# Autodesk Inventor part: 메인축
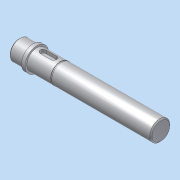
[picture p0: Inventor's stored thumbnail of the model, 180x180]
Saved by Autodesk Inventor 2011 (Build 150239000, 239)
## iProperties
Company: 한국ATC센터
Created: 2014-12
Part Number: 메인축
Document SubType Name: Modeling
Designer: KYOUNG IL JANG
Density: 1 g/cm^3
Mass: 27.2374 g
Surface Area: 71.2962 cm^2
Volume: 27.2374 cm^3
Author: KYOUNG IL JANG
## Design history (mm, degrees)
sketch "스케치1"
  geometry: L1 (0, 0)-(120, 0); L2 (0, 0)-(0, 7.5); L3 (1, 8.5)-(12, 8.5); L4 (12, 8.5)-(12, 10); L5 (12, 10)-(15, 10); L6 (15, 10)-(15, 8.5); L7 (15, 8.5)-(119, 8.5); L8 (120, 0)-(120, 7.5); L9 (1, 8.5)-(0, 7.5); L10 (119, 8.5)-(120, 7.5); 2 further points
  constraints: 20 end point, 4 point on line, 3 parallel, 3 perpendicular, 1 collinear, 1 horizontal
  dimensions: "d0" = 12 distance of point (0, 8.5) L3.end; "d1" = 17 diameter of L3 L1; "d2" = 20 diameter of L5 L1; "d3" = 17 diameter of L7 L1; "d4" = 3 distance of L4.end L5.end; "d5" = 120 distance of L1.start L1.end; "d6" = 1 distance of L3.start point (0, 8.5); "d7" = 1 distance of L2.end point (0, 8.5) (= d6); "d8" = 1 distance of L7.end point (120, 8.5) (= d6); "d9" = 1 distance of L8.end point (120, 8.5) (= d8)
revolve "회전1" sketch "스케치1" stored, may be unused: angle "d10" = 90 deg
node "작업 평면1"
sketch "스케치2"
  geometry: L1 (-46.5, 2.5)-(-37.5, 2.5); L2 (-37.5, -2.5)-(-46.5, -2.5); L3 (-52, -10)-(-52, 10) reference; A1 r 2.5 centre (-37.5, 0) between (-37.5, -2.5) and (-37.5, 2.5); A2 r 2.5 centre (-46.5, 0) between (-46.5, 2.5) and (-46.5, -2.5); 1 further point
  constraints: 4 end point, 4 point on circle, 4 tangent, 2 centre point, 1 horizontal, 1 horizontal alignment, 1 parallel
  dimensions: "d11" = 5 distance between parallel lines of L2 L1; "d12" = 3 distance edge to line of A2 L3; "d13" = 14 dimension on A1 A2
extrude "돌출1" cut sketch "스케치2" distance "d14" = 3; taper "d15" = 0 deg
sketch "스케치3"
  geometry: L1 (15, 8.5)-(119, 8.5) reference; L2 (35, 8.5)-(36.15, 8.5); L3 (36.15, 8.5)-(36.15, 8.1); L4 (36.15, 8.1)-(35, 8.1); L5 (35, 8.1)-(35, 8.5); L6 (15, -10)-(15, 10) reference; L7 (-23.8, 0)-(142.8, 0) reference; 1 further point
  constraints: 8 end point, 2 parallel, 1 horizontal, 1 perpendicular, 1 point on line
  dimensions: "d16" = 1.15 distance of L3.end L4.end; "d17" = 20 distance between parallel lines of L5 L6; "d18" = 8.1 distance from line of L4 point (0, 0)
revolve "회전2" sketch "스케치3" stored, may be unused: angle "d19" = 90 deg
node "솔리드1"
